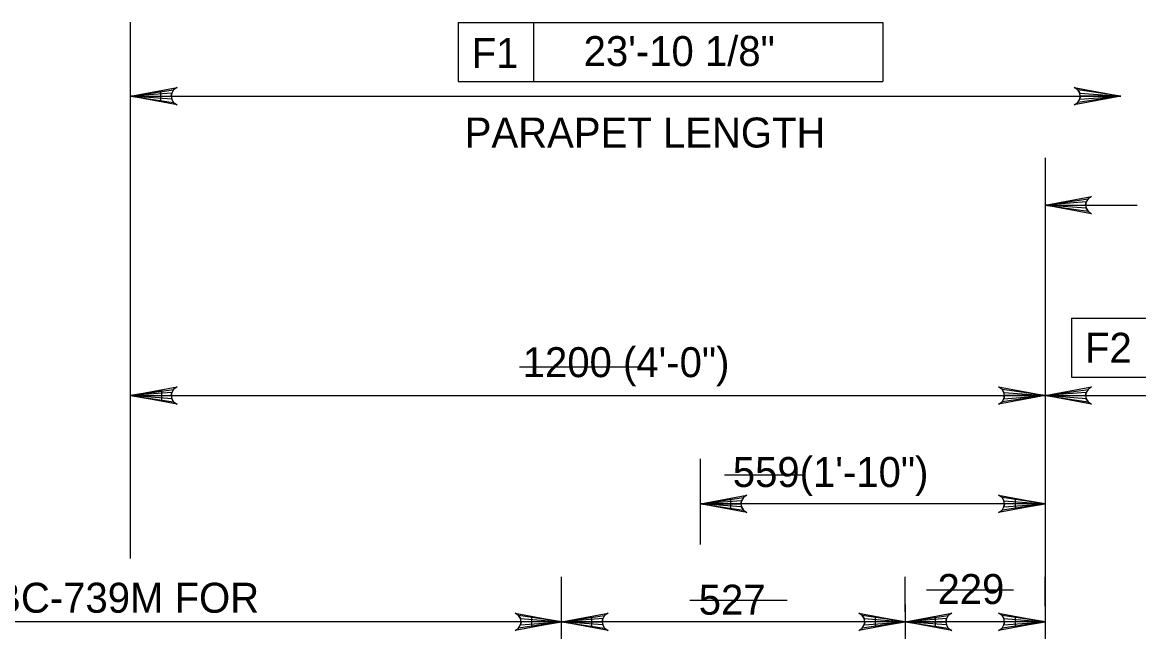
# Model space of a CAD drawing. Extents: x 179 to 454, y -271 to 54.
# Drawn here: x 365.182 to 369.653, y -11.865 to -9.424 of the extents above; entities that cross this region are included whole.
import ezdxf

# ---------------------------------------------------------------- set-up
doc = ezdxf.new("R2010")
doc.units = 0
doc.layers.add('Level 3', color=7, linetype='Continuous')
doc.layers.add('Level 41', color=7, linetype='Continuous')

msp = doc.modelspace()

# ---------------------------------------------------------------- linework, layer by layer
at = {"layer": 'Level 3'}
for p, q in [((365.6163, -11.5721), (365.6163, -9.4241)), ((366.9274, -9.4254), (367.2298, -9.4254)), ((366.9274, -9.4254), (366.9274, -9.6617)), ((367.2298, -9.4254), (367.2298, -9.6617)), ((367.2298, -9.4254), (368.6282, -9.4254)), ((368.6282, -9.4254), (368.6282, -9.6617)), ((366.9274, -9.6617), (368.6282, -9.6617)), ((365.6163, -9.72), (369.5817, -9.72)), ((369.2781, -9.9667), (369.2781, -16.3403)), ((369.2781, -10.1561), (369.6468, -10.1561)), ((369.3836, -10.6093), (369.686, -10.6093)), ((369.3836, -10.6093), (369.3836, -10.8455)), ((369.3836, -10.8455), (370.7788, -10.8455)), ((365.6163, -10.9191), (369.2781, -10.9191)), ((369.2781, -10.9191), (373.8082, -10.9191)), ((367.8979, -11.5162), (367.8979, -11.1725)), ((369.2781, -11.3525), (367.8979, -11.3525)), ((367.342, -12.7536), (367.342, -11.6451)), ((368.7183, -11.785), (368.7183, -11.6451)), ((369.2781, -11.7626), (369.2781, -11.6451)), ((368.7183, -11.7564), (368.7183, -12.3434)), ((367.3421, -11.8251), (363.8567, -11.8251)), ((368.7183, -11.8251), (367.3421, -11.8251)), ((369.2781, -11.8251), (368.7183, -11.8251))]:
    msp.add_line(p, q, dxfattribs=at)
for points in [[(365.6163, -9.72), (365.8028, -9.6851), (365.7884, -9.695), (365.781, -9.7075), (365.7788, -9.72), (365.781, -9.7325), (365.7884, -9.745), (365.8028, -9.7549), (365.6163, -9.72), (365.7884, -9.745), (365.781, -9.7325), (365.6163, -9.72), (365.7788, -9.72), (365.781, -9.7075), (365.6163, -9.72), (365.7884, -9.695)], [(369.5817, -9.72), (369.3952, -9.7549), (369.4096, -9.745), (369.417, -9.7325), (369.4192, -9.72), (369.417, -9.7075), (369.4096, -9.695), (369.3952, -9.6851), (369.5817, -9.72), (369.4096, -9.695), (369.417, -9.7075), (369.5817, -9.72), (369.4192, -9.72), (369.417, -9.7325), (369.5817, -9.72), (369.4096, -9.745)], [(369.2781, -10.1561), (369.4645, -10.1212), (369.4502, -10.1311), (369.4427, -10.1436), (369.4406, -10.1561), (369.4427, -10.1686), (369.4502, -10.1811), (369.4645, -10.191), (369.2781, -10.1561), (369.4502, -10.1811), (369.4427, -10.1686), (369.2781, -10.1561), (369.4406, -10.1561), (369.4427, -10.1436), (369.2781, -10.1561), (369.4502, -10.1311)], [(365.6163, -10.9191), (365.8028, -10.8842), (365.7884, -10.8941), (365.781, -10.9066), (365.7788, -10.9191), (365.781, -10.9316), (365.7884, -10.9441), (365.8028, -10.954), (365.6163, -10.9191), (365.7884, -10.9441), (365.781, -10.9316), (365.6163, -10.9191), (365.7788, -10.9191), (365.781, -10.9066), (365.6163, -10.9191), (365.7884, -10.8941)], [(369.2781, -10.9191), (369.0917, -10.954), (369.106, -10.9441), (369.1134, -10.9316), (369.1156, -10.9191), (369.1134, -10.9066), (369.106, -10.8941), (369.0917, -10.8842), (369.2781, -10.9191), (369.106, -10.8941), (369.1134, -10.9066), (369.2781, -10.9191), (369.1156, -10.9191), (369.1134, -10.9316), (369.2781, -10.9191), (369.106, -10.9441)], [(369.2781, -10.9191), (369.4645, -10.8842), (369.4502, -10.8941), (369.4427, -10.9066), (369.4406, -10.9191), (369.4427, -10.9316), (369.4502, -10.9441), (369.4645, -10.954), (369.2781, -10.9191), (369.4502, -10.9441), (369.4427, -10.9316), (369.2781, -10.9191), (369.4406, -10.9191), (369.4427, -10.9066), (369.2781, -10.9191), (369.4502, -10.8941)], [(367.8979, -11.3525), (368.0843, -11.3176), (368.07, -11.3275), (368.0626, -11.34), (368.0604, -11.3525), (368.0626, -11.365), (368.07, -11.3775), (368.0843, -11.3874), (367.8979, -11.3525), (368.07, -11.3775), (368.0626, -11.365), (367.8979, -11.3525), (368.0604, -11.3525), (368.0626, -11.34), (367.8979, -11.3525), (368.07, -11.3275)], [(369.2781, -11.3525), (369.0917, -11.3874), (369.106, -11.3775), (369.1134, -11.365), (369.1156, -11.3525), (369.1134, -11.34), (369.106, -11.3275), (369.0917, -11.3176), (369.2781, -11.3525), (369.106, -11.3275), (369.1134, -11.34), (369.2781, -11.3525), (369.1156, -11.3525), (369.1134, -11.365), (369.2781, -11.3525), (369.106, -11.3775)], [(367.3421, -11.8251), (367.1557, -11.86), (367.17, -11.8501), (367.1774, -11.8376), (367.1796, -11.8251), (367.1774, -11.8126), (367.17, -11.8001), (367.1557, -11.7902), (367.3421, -11.8251), (367.17, -11.8001), (367.1774, -11.8126), (367.3421, -11.8251), (367.1796, -11.8251), (367.1774, -11.8376), (367.3421, -11.8251), (367.17, -11.8501)], [(367.3421, -11.8251), (367.5285, -11.7902), (367.5142, -11.8001), (367.5068, -11.8126), (367.5046, -11.8251), (367.5068, -11.8376), (367.5142, -11.8501), (367.5285, -11.86), (367.3421, -11.8251), (367.5142, -11.8501), (367.5068, -11.8376), (367.3421, -11.8251), (367.5046, -11.8251), (367.5068, -11.8126), (367.3421, -11.8251), (367.5142, -11.8001)], [(368.7183, -11.8251), (368.5319, -11.86), (368.5462, -11.8501), (368.5537, -11.8376), (368.5558, -11.8251), (368.5537, -11.8126), (368.5462, -11.8001), (368.5319, -11.7902), (368.7183, -11.8251), (368.5462, -11.8001), (368.5537, -11.8126), (368.7183, -11.8251), (368.5558, -11.8251), (368.5537, -11.8376), (368.7183, -11.8251), (368.5462, -11.8501)], [(368.7183, -11.8251), (368.9047, -11.7902), (368.8904, -11.8001), (368.883, -11.8126), (368.8808, -11.8251), (368.883, -11.8376), (368.8904, -11.8501), (368.9047, -11.86), (368.7183, -11.8251), (368.8904, -11.8501), (368.883, -11.8376), (368.7183, -11.8251), (368.8808, -11.8251), (368.883, -11.8126), (368.7183, -11.8251), (368.8904, -11.8001)], [(369.2781, -11.8251), (369.0917, -11.86), (369.106, -11.8501), (369.1134, -11.8376), (369.1156, -11.8251), (369.1134, -11.8126), (369.106, -11.8001), (369.0917, -11.7902), (369.2781, -11.8251), (369.106, -11.8001), (369.1134, -11.8126), (369.2781, -11.8251), (369.1156, -11.8251), (369.1134, -11.8376), (369.2781, -11.8251), (369.106, -11.8501)]]:
    msp.add_lwpolyline(points, dxfattribs=at)
for points in [[(365.7363, -9.7), (365.7363, -9.74), (365.6163, -9.72)], [(365.7413, -10.9399), (365.7413, -10.8982), (365.6163, -10.9191)], [(368.0179, -11.3325), (368.0179, -11.3725), (367.8979, -11.3525)], [(369.1581, -11.3325), (369.1581, -11.3725), (369.2781, -11.3525)], [(367.2221, -11.8051), (367.2221, -11.8451), (367.3421, -11.8251)], [(367.4621, -11.8051), (367.4621, -11.8451), (367.3421, -11.8251)], [(368.5983, -11.8051), (368.5983, -11.8451), (368.7183, -11.8251)], [(368.8383, -11.8051), (368.8383, -11.8451), (368.7183, -11.8251)], [(369.1581, -11.8051), (369.1581, -11.8451), (369.2781, -11.8251)]]:
    msp.add_lwpolyline(points, close=True, dxfattribs=at)
at = {"layer": 'Level 41'}
for p, q in [((367.173, -10.8042), (367.6606, -10.8042)), ((367.995, -11.2364), (368.3155, -11.2364)), ((368.8032, -11.6965), (369.1515, -11.6965)), ((367.8557, -11.7384), (368.2458, -11.7384))]:
    msp.add_line(p, q, dxfattribs=at)

# ---------------------------------------------------------------- texts
at = {"layer": 'Level 3'}
for s, p in [('F1', (366.982, -9.6067)), ('F2', (369.438, -10.7874))]:
    msp.add_text(s, height=0.12, rotation=359.9382, dxfattribs=at).set_placement(p)
for s, p in [('PARAPET LENGTH', (366.9541, -9.9255)), ('1200 (4\'-0")', (367.1863, -10.8453)), ('559(1\'-10")', (368.0277, -11.2852)), ('   REFER TO BC-739M FOR', (364.0802, -11.7888)), ('229', (368.8475, -11.7539)), ('527', (367.8912, -11.7967))]:
    msp.add_text(s, height=0.12, dxfattribs=at).set_placement(p)
at = {"layer": 'Level 41'}
msp.add_text('23\'-10 1/8"', height=0.12, dxfattribs=at).set_placement((367.4304, -9.5993))

doc.saveas('drawing.dxf')
